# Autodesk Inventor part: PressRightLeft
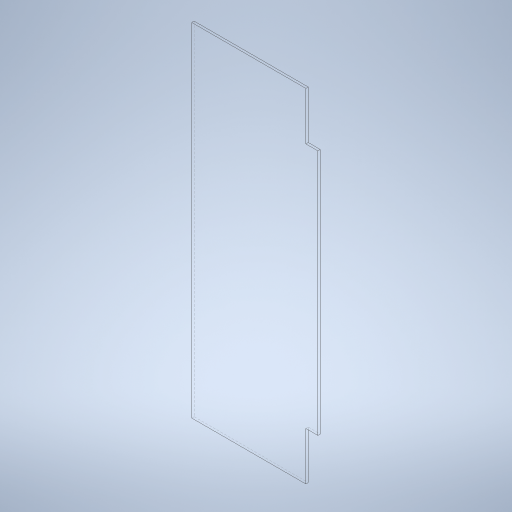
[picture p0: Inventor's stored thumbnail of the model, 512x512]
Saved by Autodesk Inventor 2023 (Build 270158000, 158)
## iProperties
Created: 2023-11
Part Number: PressRightLeft
Material: Generic
Document SubType Name: Modeling
Designer: tornqvih
Density: 1 g/cm^3
Appearance: Default
Author: tornqvih
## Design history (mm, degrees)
sketch "Sketch1"
  geometry: L1 (0, 0)-(95, 0); L2 (95, -245)-(95, -285); L3 (0, -285)-(0, 0); L4 (105, -40)-(105, -245); L5 (105, -245)-(95, -245); L6 (95, 0)-(95, -40); L7 (95, -285)-(0, -285); L8 (95, -40)-(105, -40)
  constraints: 16 end point, 3 horizontal, 3 vertical, 2 parallel, 1 vertical alignment
  dimensions: "d4" = 105 distance between parallel lines of L4 L3; "d5" = 285 distance of L3.start L1.start; "d6" = 40 distance of L1.end L6.end; "d7" = 40 distance of L2.start L2.end; "d8" = 10 distance of L6.end L4.start
extrude "Extrusion1" new body sketch "Sketch1" distance "d2" = 2; taper "d3" = 0 deg
body "Solid1"
